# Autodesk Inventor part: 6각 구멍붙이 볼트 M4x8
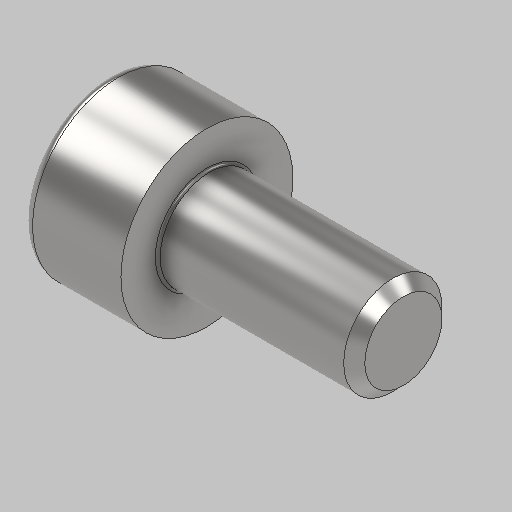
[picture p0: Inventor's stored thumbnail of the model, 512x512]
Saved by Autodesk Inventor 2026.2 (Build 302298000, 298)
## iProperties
Created: 2026-06
Part Number: 6각 구멍붙이 볼트 M4x8
Material: 강철, 연강
Description: 6각머리 태핑 나사
Document SubType Name: Modeling
Designer: sec7
Density: 7.85 g/cm^3
Appearance: 기본값
Sending System: Autodesk Inventor 2027
Preprocessor: ST-DEVELOPER v20.1
Author: jhkim
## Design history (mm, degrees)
feature "Solid1"
node "솔리드1"
